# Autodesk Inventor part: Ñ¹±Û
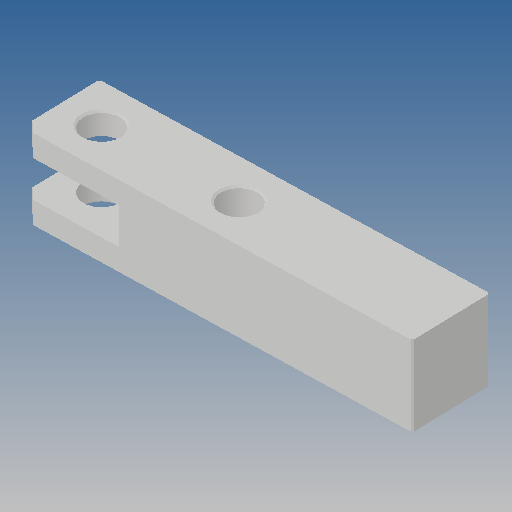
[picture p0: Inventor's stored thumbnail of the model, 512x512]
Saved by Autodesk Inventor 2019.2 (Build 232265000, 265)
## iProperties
Created: 2013-07
Part Number: Ñ¹±Û
Material: Ogólny
Document SubType Name: Modeling
Designer: CADENGINEERING4
Density: 1 g/cm^3
Appearance: Domyślna
Author: CADENGINEERING4
Revision Number: ÈÎºÎ
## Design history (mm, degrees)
feature "CALC80-Ñ¹±Û.bak-1-solid1"
node "Bryła1"
